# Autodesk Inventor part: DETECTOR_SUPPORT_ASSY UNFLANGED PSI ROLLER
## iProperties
Shininess: 64.0
Length Units: 11272
Angle Units: 11279
Time Units: 11290
Mass Units: 11286
Length Display Precision: 3
Angle Display Precision: 2
Compacted: True
Part Number: DETECTOR_SUPPORT_ASSY UNFLANGED PSI ROLLER
Document SubType Name: Modeling
Created: 2004-08
Designer: John Blackburn
Material: MILD_STEEL
Manufacturer: Standard
Standards Organization: Custom
Density: 0.0
Volumn: 0.0
Area: 0.0
PropertySet Name: Model Information
Control State: 0
Master: False
Checked Out: False
Author: John Blackburn
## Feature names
1. ExtrusionBlind1
2. Fillet1
3. Shell1
4. ExtrusionBlind2
5. ExtrusionBlind3
6. ExtrusionBlind4
7. ExtrusionBlind5
8. AM_HOLE_SI0029_1 [Hole]
9. Rectangular Pattern1
10. ExtrusionMidplane1
11. ExtrusionMidplane2
